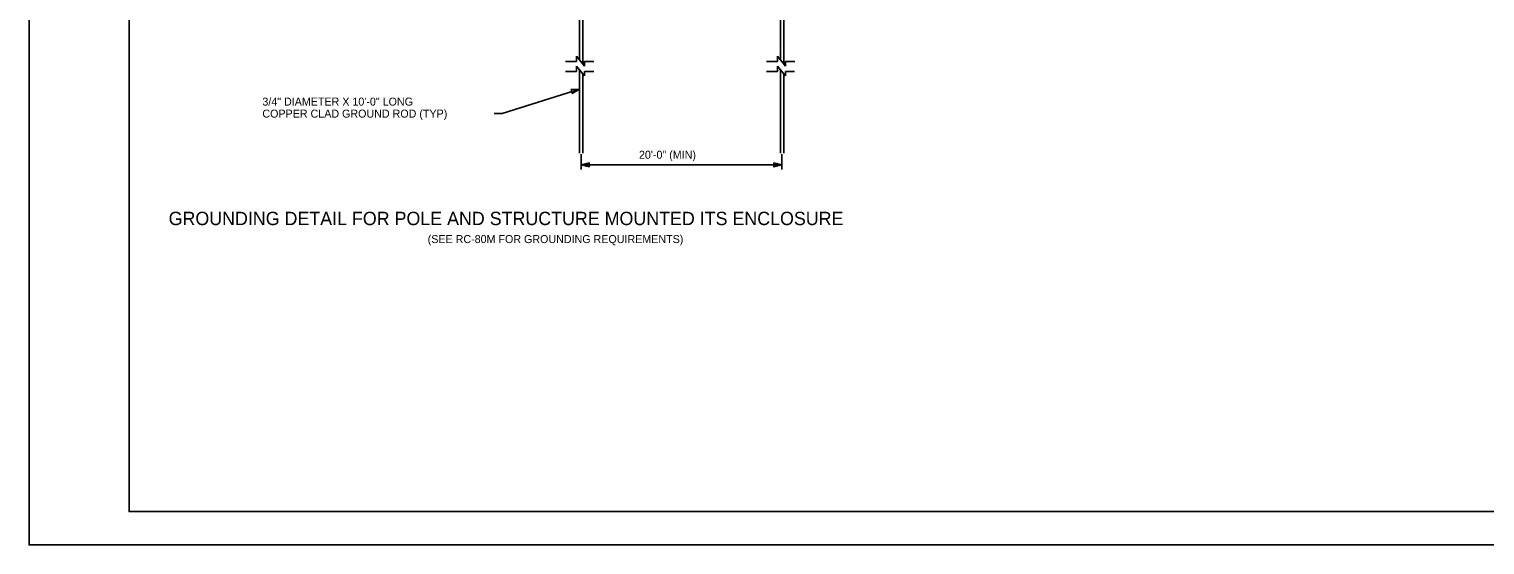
# Model space of a CAD drawing. Extents: x 1299104.8 to 1299141.6, y 239639.8 to 239661.8.
# Drawn here: x 1299104.8 to 1299126.63, y 239639.79 to 239647.52 of the extents above; entities that cross this region are included whole.
import ezdxf

# ---------------------------------------------------------------- set-up
doc = ezdxf.new("R2010")
doc.units = 0
for name, color, linetype in [('DIM TXT', 7, 'Continuous'), ('GS_plotshape_p', 7, 'Continuous'), ('Level 1', 7, 'Continuous')]:
    doc.layers.add(name, color=color, linetype=linetype)

msp = doc.modelspace()

# ---------------------------------------------------------------- linework, layer by layer
at = {"layer": 'DIM TXT'}
for p, q in [((1299113.053, 239649.851), (1299113.053, 239647.063)), ((1299113.103, 239649.851), (1299113.103, 239647.003)), ((1299116.067, 239649.851), (1299116.067, 239647.063)), ((1299116.117, 239649.851), (1299116.117, 239647.003)), ((1299112.847, 239647.035), (1299113.011, 239647.035)), ((1299113.011, 239647.035), (1299113.01, 239647.114)), ((1299113.01, 239647.114), (1299113.076, 239647.035)), ((1299113.01, 239646.886), (1299113.01, 239646.965)), ((1299113.01, 239646.965), (1299113.075, 239646.886)), ((1299113.053, 239646.912), (1299113.053, 239645.659)), ((1299113.132, 239646.967), (1299113.076, 239647.035)), ((1299113.268, 239647.036), (1299113.132, 239647.036)), ((1299113.132, 239647.036), (1299113.132, 239646.967)), ((1299115.861, 239647.035), (1299116.024, 239647.035)), ((1299116.023, 239646.886), (1299116.023, 239646.965)), ((1299116.023, 239646.965), (1299116.088, 239646.886)), ((1299116.024, 239647.035), (1299116.024, 239647.114)), ((1299116.024, 239647.114), (1299116.089, 239647.035)), ((1299116.067, 239646.912), (1299116.067, 239645.659)), ((1299116.146, 239646.967), (1299116.089, 239647.035)), ((1299116.282, 239647.036), (1299116.146, 239647.036)), ((1299116.146, 239647.036), (1299116.146, 239646.967)), ((1299112.846, 239646.885), (1299113.01, 239646.886)), ((1299113.132, 239646.818), (1299113.075, 239646.886)), ((1299113.103, 239646.852), (1299113.103, 239645.659)), ((1299113.268, 239646.886), (1299113.131, 239646.886)), ((1299113.131, 239646.886), (1299113.132, 239646.818)), ((1299115.86, 239646.885), (1299116.023, 239646.886)), ((1299116.145, 239646.818), (1299116.088, 239646.886)), ((1299116.117, 239646.852), (1299116.117, 239645.659)), ((1299116.281, 239646.886), (1299116.145, 239646.886)), ((1299116.145, 239646.886), (1299116.145, 239646.818)), ((1299113.078, 239645.644), (1299113.078, 239645.417)), ((1299116.091, 239645.644), (1299116.091, 239645.417)), ((1299113.078, 239645.485), (1299116.091, 239645.485))]:
    msp.add_line(p, q, dxfattribs=at)
msp.add_lwpolyline([(1299111.774, 239646.257), (1299111.897, 239646.257), (1299113.053, 239646.62)], dxfattribs=at)
for points in [[(1299112.93, 239646.614), (1299113.053, 239646.619), (1299112.946, 239646.557)], [(1299113.198, 239645.455), (1299113.078, 239645.485), (1299113.198, 239645.515)], [(1299115.971, 239645.516), (1299116.091, 239645.485), (1299115.971, 239645.456)]]:
    msp.add_lwpolyline(points, close=True, dxfattribs=at)
at = {"layer": 'GS_plotshape_p'}
msp.add_lwpolyline([(1299104.802, 239661.791), (1299138.802, 239661.791), (1299138.802, 239639.791), (1299104.802, 239639.791)], close=True, dxfattribs=at)
at = {"layer": 'Level 1'}
msp.add_lwpolyline([(1299138.302, 239640.291), (1299106.302, 239640.291), (1299106.302, 239661.291), (1299138.302, 239661.291)], close=True, dxfattribs=at)

# ---------------------------------------------------------------- texts
at = {"layer": 'DIM TXT'}
for s, height, p in [('3/4" DIAMETER X 10\'-0" LONG', 0.12, (1299108.3, 239646.374)), ('COPPER CLAD GROUND ROD (TYP)', 0.12, (1299108.3, 239646.194)), ('20\'-0" (MIN)', 0.12, (1299113.947, 239645.578)), ('GROUNDING DETAIL FOR POLE AND STRUCTURE MOUNTED ITS ENCLOSURE', 0.2, (1299106.894, 239644.583)), ('(SEE RC-80M FOR GROUNDING REQUIREMENTS)', 0.12, (1299110.779, 239644.314))]:
    msp.add_text(s, height=height, dxfattribs=at).set_placement(p)

doc.saveas('drawing.dxf')
